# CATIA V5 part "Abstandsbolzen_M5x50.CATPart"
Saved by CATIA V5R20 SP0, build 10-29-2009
Part number: Abstandsbolzen_M5x50
Bounding box of the stored display mesh (mm): x -4.619 to 4.619, y -4 to 4, z -10 to 50
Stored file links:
  C:\Users\Andi\Desktop\Offene Projekte\Plasmacutter\Z-Achse\Abstandsbolzen_M5x50.CATPart
  C:\Program Files\Dassault Systemes\B20\win_b64\reffiles\standard\MetricThickPitch.txt
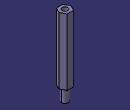
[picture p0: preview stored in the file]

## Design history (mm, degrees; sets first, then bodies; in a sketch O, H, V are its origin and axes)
Body1 (main body)
  Sketch1 on xy-plane, origin (0, 0, 0), H (1, 0, 0), V (0, 1, 0)
    point P1 (4.6188, 0)
    point P2 (2.3094, 4)
    point P3 (-2.3094, 4)
    point P4 (-4.6188, 0)
    point P5 (-2.3094, -4)
    point P6 (2.3094, -4)
    point P7 (3.4641, 2)
    line L1 (4.6188, 0) -> (2.3094, 4)
    line L2 (2.3094, 4) -> (-2.3094, 4)
    line L3 (-2.3094, 4) -> (-4.6188, 0)
    line L4 (-4.6188, 0) -> (-2.3094, -4)
    line L5 (-2.3094, -4) -> (2.3094, -4)
    line L6 (2.3094, -4) -> (4.6188, 0)
    construction line L7 (0, 0) -> (3.4641, 2)
    construction circle A1 centre (0, 0) radius 4.6188
    construction arc A2 centre (-2.3094, -4) radius 4.6188 from (-4.6188, 0) to (2.3094, -4) cw
    construction arc A3 centre (2.3094, 4) radius 4.6188 from (-2.3094, 4) to (4.6188, 0) ccw
    distance L1 L4 = 8
    coincidence: A1 P1, A1 P2, A1 P3, A1 P4, A1 P5, A1 P6, A2 O, A3 O
    midpoint: P7 L1
    horizontal: L2 H
  Pad1: profile Sketch1, direction (0, 0, 1), length 50
  Sketch2 on start face of Pad1, origin (0, 0, 0), H (1, 0, 0), V (0, -1, 0)
    circle A1 centre (0, 0) radius 2.5
    radius A1 = 2.5
  Pad2: profile Sketch2, direction (0, 0, -1), length 10
  Sketch3 on end face of Pad1, origin (-0.193, 0, 50), H (1, 0, 0), V (0, 1, 0)
    point P1 (0.193, 0)
    reference intersected line E1 through (0.193, 0) direction (0, 1) from yz-plane
    reference intersected line E2 through (0, 0) direction (-1, 0) from zx-plane
    coincidence: P1 E1, E2 P1
  Hole1: placed by Sketch3, at (0, 0, 50) direction (0, 0, -1), diameter 4.134, depth 10, V-bottom angle 120, threaded "M5", thread diameter 5, thread depth 7, pitch 0.8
